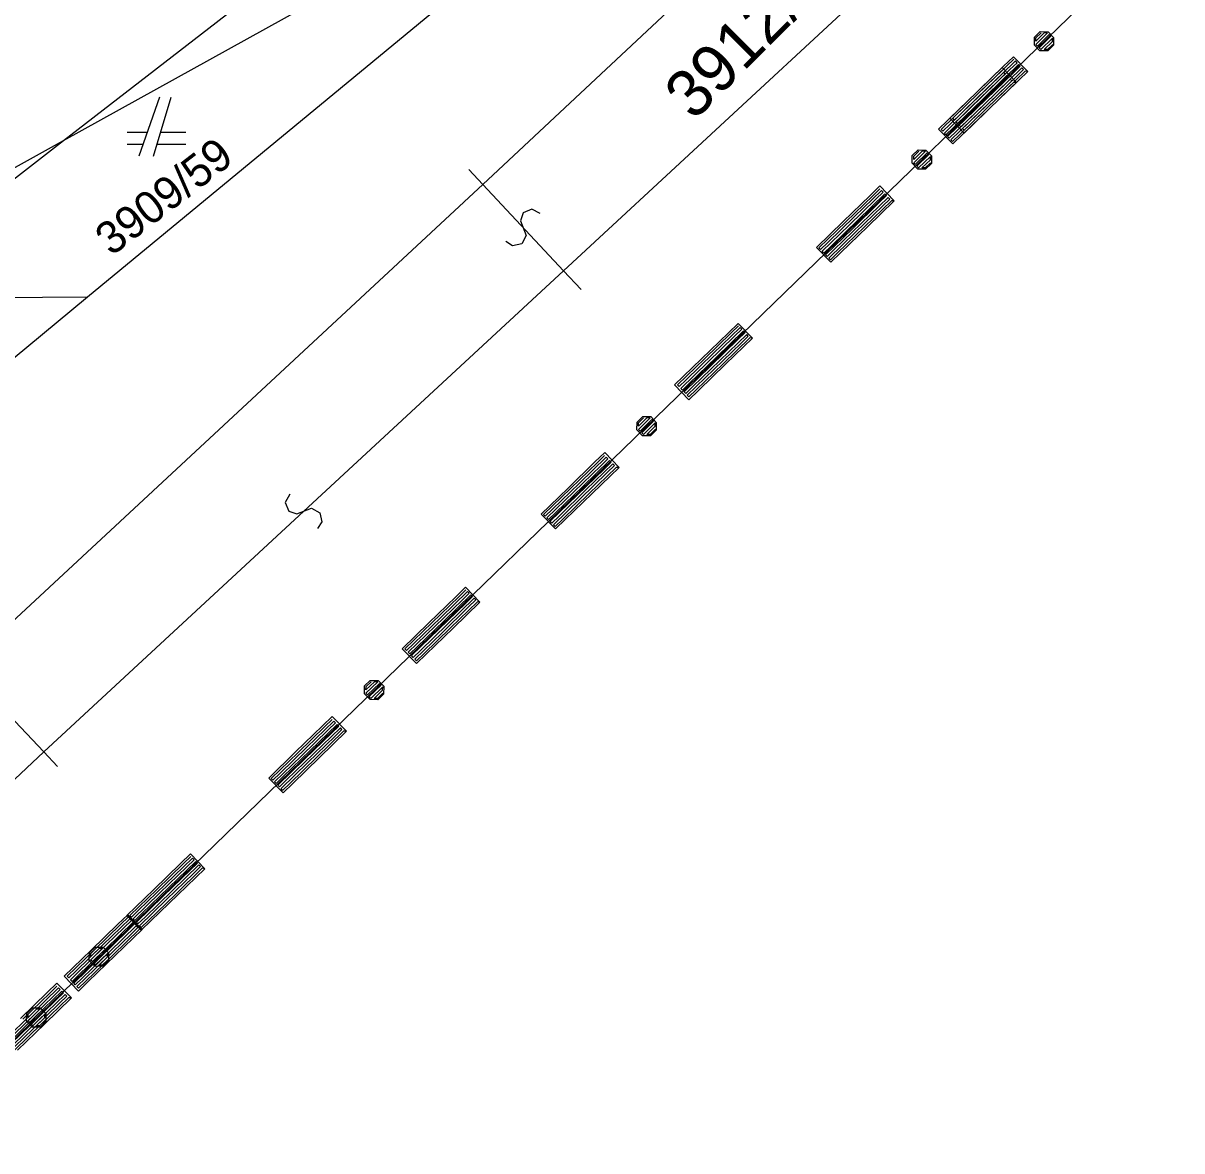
# Model space of a CAD drawing. Extents: x -266179 to -264727, y -1243225 to -1241702.
# Drawn here: x -265525.42 to -265486.12, y -1243104.16 to -1243065.9 of the extents above; entities that cross this region are included whole.
import ezdxf

# ---------------------------------------------------------------- set-up
doc = ezdxf.new("R2010")
doc.units = 0
for name, color, linetype in [('Vrstva 1', 7, 'Continuous'), ('Vrstva 19', 7, 'Continuous'), ('Vrstva 2', 7, 'Continuous'), ('Vrstva 21', 7, 'Continuous')]:
    doc.layers.add(name, color=color, linetype=linetype)

msp = doc.modelspace()

# ---------------------------------------------------------------- linework, layer by layer
at = {"layer": 'Vrstva 1'}
for p, q in [((-265524.05, -1243069.88), (-265501.93, -1243057.61)), ((-265501.93, -1243057.61), (-265523.24, -1243075.2)), ((-265486.12, -1243061.99), (-265499.6, -1243075.05)), ((-265520.8, -1243068.41), (-265521.5, -1243070.41)), ((-265521, -1243070.41), (-265520.4, -1243068.41)), ((-265521.22, -1243069.61), (-265521.9, -1243069.61)), ((-265519.9, -1243069.61), (-265520.76, -1243069.61)), ((-265533.77, -1243075.27), (-265524.05, -1243069.88)), ((-265521.9, -1243070.01), (-265521.36, -1243070.01)), ((-265520.88, -1243070.01), (-265519.9, -1243070.01)), ((-265523.24, -1243075.2), (-265536.52, -1243086.16)), ((-265523.24, -1243075.2), (-265530.95, -1243075.25)), ((-265499.6, -1243075.05), (-265518.18, -1243093.05)), ((-265518.18, -1243093.05), (-265529.64, -1243104.16))]:
    msp.add_line(p, q, dxfattribs=at)
at = {"layer": 'Vrstva 19'}
for p, q in [((-265486.12, -1243061.99), (-265499.6, -1243075.05)), ((-265499.6, -1243075.05), (-265518.18, -1243093.05)), ((-265518.18, -1243093.05), (-265529.64, -1243104.16))]:
    msp.add_line(p, q, dxfattribs=at)
for points in [[(-265490.472, -1243066.652), (-265490.666, -1243066.84), (-265490.935, -1243066.836), (-265491.123, -1243066.642), (-265491.118, -1243066.373), (-265490.925, -1243066.185), (-265490.656, -1243066.19), (-265490.468, -1243066.384), (-265490.472, -1243066.652), (-265490.507, -1243066.631), (-265490.68, -1243066.798), (-265490.793, -1243066.796), (-265490.506, -1243066.517), (-265490.504, -1243066.404), (-265490.906, -1243066.794), (-265490.962, -1243066.736), (-265490.559, -1243066.347), (-265490.615, -1243066.289), (-265491.017, -1243066.679), (-265491.073, -1243066.621), (-265490.671, -1243066.232), (-265490.784, -1243066.23), (-265491.071, -1243066.508), (-265491.069, -1243066.395), (-265490.897, -1243066.228)], [(-265491.73, -1243067.912), (-265492.642, -1243068.796), (-265493.555, -1243069.679), (-265493.885, -1243069.999), (-265494.372, -1243069.497), (-265493.46, -1243068.613), (-265492.548, -1243067.729), (-265492.217, -1243067.409), (-265491.73, -1243067.912), (-265491.829, -1243067.911), (-265492.741, -1243068.794), (-265493.654, -1243069.678), (-265493.898, -1243069.914), (-265493.953, -1243069.857), (-265493.041, -1243068.973), (-265492.129, -1243068.09), (-265491.885, -1243067.853), (-265491.94, -1243067.796), (-265492.853, -1243068.679), (-265493.765, -1243069.563), (-265494.009, -1243069.799), (-265494.065, -1243069.742), (-265493.153, -1243068.858), (-265492.24, -1243067.975), (-265491.996, -1243067.738), (-265492.052, -1243067.681), (-265492.964, -1243068.564), (-265493.876, -1243069.448), (-265494.12, -1243069.684), (-265494.176, -1243069.627), (-265493.264, -1243068.743), (-265492.352, -1243067.86), (-265492.107, -1243067.623), (-265492.163, -1243067.566), (-265493.075, -1243068.449), (-265493.988, -1243069.333), (-265494.232, -1243069.569), (-265494.287, -1243069.512), (-265493.375, -1243068.628), (-265492.463, -1243067.745), (-265492.219, -1243067.508)], [(-265491.348, -1243067.543), (-265492.26, -1243068.427), (-265493.172, -1243069.311), (-265493.503, -1243069.631), (-265493.99, -1243069.128), (-265493.078, -1243068.244), (-265492.165, -1243067.361), (-265491.835, -1243067.041), (-265491.348, -1243067.543), (-265491.433, -1243067.528), (-265492.345, -1243068.412), (-265493.257, -1243069.295), (-265493.501, -1243069.532), (-265493.557, -1243069.474), (-265492.645, -1243068.591), (-265491.732, -1243067.707), (-265491.488, -1243067.471), (-265491.544, -1243067.413), (-265492.456, -1243068.297), (-265493.368, -1243069.18), (-265493.613, -1243069.417), (-265493.668, -1243069.359), (-265492.756, -1243068.476), (-265491.844, -1243067.592), (-265491.6, -1243067.356), (-265491.655, -1243067.298), (-265492.567, -1243068.182), (-265493.48, -1243069.065), (-265493.724, -1243069.302), (-265493.78, -1243069.244), (-265492.867, -1243068.361), (-265491.955, -1243067.477), (-265491.711, -1243067.241), (-265491.767, -1243067.183), (-265492.679, -1243068.067), (-265493.591, -1243068.95), (-265493.835, -1243069.187), (-265493.891, -1243069.129), (-265492.979, -1243068.246), (-265492.066, -1243067.362), (-265491.822, -1243067.126)], [(-265494.616, -1243070.667), (-265494.81, -1243070.854), (-265495.078, -1243070.85), (-265495.266, -1243070.656), (-265495.262, -1243070.387), (-265495.068, -1243070.2), (-265494.799, -1243070.204), (-265494.611, -1243070.398), (-265494.616, -1243070.667), (-265494.651, -1243070.645), (-265494.823, -1243070.812), (-265494.936, -1243070.81), (-265494.649, -1243070.532), (-265494.647, -1243070.419), (-265495.049, -1243070.808), (-265495.105, -1243070.751), (-265494.703, -1243070.361), (-265494.758, -1243070.304), (-265495.161, -1243070.693), (-265495.216, -1243070.636), (-265494.814, -1243070.246), (-265494.927, -1243070.244), (-265495.214, -1243070.523), (-265495.213, -1243070.409), (-265495.04, -1243070.242)], [(-265495.873, -1243071.926), (-265496.786, -1243072.81), (-265497.698, -1243073.694), (-265498.028, -1243074.014), (-265498.515, -1243073.511), (-265497.603, -1243072.627), (-265496.691, -1243071.744), (-265496.36, -1243071.424), (-265495.873, -1243071.926), (-265495.972, -1243071.925), (-265496.885, -1243072.808), (-265497.797, -1243073.692), (-265498.041, -1243073.929), (-265498.097, -1243073.871), (-265497.185, -1243072.987), (-265496.272, -1243072.104), (-265496.028, -1243071.867), (-265496.084, -1243071.81), (-265496.996, -1243072.693), (-265497.908, -1243073.577), (-265498.152, -1243073.814), (-265498.208, -1243073.756), (-265497.296, -1243072.873), (-265496.384, -1243071.989), (-265496.139, -1243071.752), (-265496.195, -1243071.695), (-265497.107, -1243072.579), (-265498.02, -1243073.462), (-265498.264, -1243073.699), (-265498.319, -1243073.641), (-265497.407, -1243072.758), (-265496.495, -1243071.874), (-265496.251, -1243071.638), (-265496.306, -1243071.58), (-265497.219, -1243072.464), (-265498.131, -1243073.347), (-265498.375, -1243073.584), (-265498.431, -1243073.526), (-265497.518, -1243072.643), (-265496.606, -1243071.759), (-265496.362, -1243071.523)], [(-265500.685, -1243076.589), (-265501.597, -1243077.473), (-265502.509, -1243078.356), (-265502.84, -1243078.676), (-265503.327, -1243078.173), (-265502.414, -1243077.29), (-265501.502, -1243076.406), (-265501.172, -1243076.086), (-265500.685, -1243076.589), (-265500.769, -1243076.574), (-265501.682, -1243077.457), (-265502.594, -1243078.341), (-265502.838, -1243078.577), (-265502.894, -1243078.52), (-265501.982, -1243077.636), (-265501.069, -1243076.753), (-265500.825, -1243076.516), (-265500.881, -1243076.459), (-265501.793, -1243077.342), (-265502.705, -1243078.226), (-265502.949, -1243078.462), (-265503.005, -1243078.405), (-265502.093, -1243077.521), (-265501.181, -1243076.638), (-265500.936, -1243076.401), (-265500.992, -1243076.344), (-265501.904, -1243077.227), (-265502.817, -1243078.111), (-265503.061, -1243078.347), (-265503.116, -1243078.29), (-265502.204, -1243077.406), (-265501.292, -1243076.523), (-265501.048, -1243076.286), (-265501.103, -1243076.229), (-265502.016, -1243077.112), (-265502.928, -1243077.996), (-265503.172, -1243078.232), (-265503.228, -1243078.175), (-265502.315, -1243077.291), (-265501.403, -1243076.408), (-265501.159, -1243076.171)], [(-265503.952, -1243079.712), (-265504.146, -1243079.9), (-265504.415, -1243079.896), (-265504.603, -1243079.702), (-265504.599, -1243079.433), (-265504.405, -1243079.245), (-265504.136, -1243079.25), (-265503.948, -1243079.444), (-265503.952, -1243079.712), (-265503.987, -1243079.69), (-265504.16, -1243079.857), (-265504.273, -1243079.856), (-265503.986, -1243079.577), (-265503.984, -1243079.464), (-265504.386, -1243079.854), (-265504.442, -1243079.796), (-265504.04, -1243079.407), (-265504.095, -1243079.349), (-265504.497, -1243079.739), (-265504.553, -1243079.681), (-265504.151, -1243079.292), (-265504.264, -1243079.29), (-265504.551, -1243079.568), (-265504.549, -1243079.455), (-265504.377, -1243079.288)], [(-265505.21, -1243080.972), (-265506.122, -1243081.856), (-265507.035, -1243082.739), (-265507.365, -1243083.059), (-265507.852, -1243082.556), (-265506.94, -1243081.673), (-265506.028, -1243080.789), (-265505.697, -1243080.469), (-265505.21, -1243080.972), (-265505.309, -1243080.971), (-265506.221, -1243081.854), (-265507.134, -1243082.738), (-265507.378, -1243082.974), (-265507.434, -1243082.917), (-265506.521, -1243082.033), (-265505.609, -1243081.15), (-265505.365, -1243080.913), (-265505.421, -1243080.856), (-265506.333, -1243081.739), (-265507.245, -1243082.623), (-265507.489, -1243082.859), (-265507.545, -1243082.802), (-265506.633, -1243081.918), (-265505.72, -1243081.035), (-265505.476, -1243080.798), (-265505.532, -1243080.741), (-265506.444, -1243081.624), (-265507.356, -1243082.508), (-265507.601, -1243082.744), (-265507.656, -1243082.687), (-265506.744, -1243081.803), (-265505.832, -1243080.92), (-265505.587, -1243080.683), (-265505.643, -1243080.626), (-265506.555, -1243081.509), (-265507.468, -1243082.393), (-265507.712, -1243082.629), (-265507.768, -1243082.572), (-265506.855, -1243081.688), (-265505.943, -1243080.805), (-265505.699, -1243080.568)], [(-265509.928, -1243085.544), (-265510.84, -1243086.427), (-265511.752, -1243087.311), (-265512.083, -1243087.631), (-265512.57, -1243087.128), (-265511.658, -1243086.244), (-265510.745, -1243085.361), (-265510.415, -1243085.041), (-265509.928, -1243085.544), (-265510.012, -1243085.528), (-265510.925, -1243086.412), (-265511.837, -1243087.295), (-265512.081, -1243087.532), (-265512.137, -1243087.474), (-265511.225, -1243086.591), (-265510.312, -1243085.707), (-265510.068, -1243085.471), (-265510.124, -1243085.413), (-265511.036, -1243086.297), (-265511.948, -1243087.18), (-265512.193, -1243087.417), (-265512.248, -1243087.359), (-265511.336, -1243086.476), (-265510.424, -1243085.592), (-265510.179, -1243085.356), (-265510.235, -1243085.298), (-265511.147, -1243086.182), (-265512.06, -1243087.065), (-265512.304, -1243087.302), (-265512.359, -1243087.244), (-265511.447, -1243086.361), (-265510.535, -1243085.477), (-265510.291, -1243085.241), (-265510.346, -1243085.183), (-265511.259, -1243086.067), (-265512.171, -1243086.95), (-265512.415, -1243087.187), (-265512.471, -1243087.129), (-265511.559, -1243086.246), (-265510.646, -1243085.362), (-265510.402, -1243085.126)], [(-265513.196, -1243088.667), (-265513.389, -1243088.855), (-265513.658, -1243088.85), (-265513.846, -1243088.656), (-265513.842, -1243088.388), (-265513.648, -1243088.2), (-265513.379, -1243088.204), (-265513.191, -1243088.398), (-265513.196, -1243088.667), (-265513.231, -1243088.645), (-265513.403, -1243088.812), (-265513.516, -1243088.81), (-265513.229, -1243088.532), (-265513.227, -1243088.419), (-265513.629, -1243088.808), (-265513.685, -1243088.751), (-265513.283, -1243088.361), (-265513.338, -1243088.304), (-265513.74, -1243088.693), (-265513.796, -1243088.636), (-265513.394, -1243088.246), (-265513.507, -1243088.244), (-265513.794, -1243088.523), (-265513.793, -1243088.41), (-265513.62, -1243088.243)], [(-265514.453, -1243089.927), (-265515.366, -1243090.81), (-265516.278, -1243091.694), (-265516.608, -1243092.014), (-265517.095, -1243091.511), (-265516.183, -1243090.627), (-265515.271, -1243089.744), (-265514.94, -1243089.424), (-265514.453, -1243089.927), (-265514.552, -1243089.925), (-265515.465, -1243090.809), (-265516.377, -1243091.692), (-265516.621, -1243091.929), (-265516.677, -1243091.871), (-265515.764, -1243090.988), (-265514.852, -1243090.104), (-265514.608, -1243089.868), (-265514.664, -1243089.81), (-265515.576, -1243090.694), (-265516.488, -1243091.577), (-265516.732, -1243091.814), (-265516.788, -1243091.756), (-265515.876, -1243090.873), (-265514.963, -1243089.989), (-265514.719, -1243089.753), (-265514.775, -1243089.695), (-265515.687, -1243090.579), (-265516.599, -1243091.462), (-265516.844, -1243091.699), (-265516.899, -1243091.641), (-265515.987, -1243090.758), (-265515.075, -1243089.874), (-265514.831, -1243089.638), (-265514.886, -1243089.58), (-265515.798, -1243090.464), (-265516.711, -1243091.347), (-265516.955, -1243091.584), (-265517.011, -1243091.526), (-265516.098, -1243090.643), (-265515.186, -1243089.759), (-265514.942, -1243089.523)], [(-265519.263, -1243094.591), (-265520.175, -1243095.474), (-265521.088, -1243096.358), (-265521.418, -1243096.678), (-265521.905, -1243096.175), (-265520.993, -1243095.291), (-265520.081, -1243094.408), (-265519.75, -1243094.088), (-265519.263, -1243094.591), (-265519.348, -1243094.575), (-265520.26, -1243095.459), (-265521.172, -1243096.342), (-265521.417, -1243096.579), (-265521.472, -1243096.521), (-265520.56, -1243095.638), (-265519.648, -1243094.754), (-265519.403, -1243094.518), (-265519.459, -1243094.46), (-265520.371, -1243095.344), (-265521.284, -1243096.227), (-265521.528, -1243096.464), (-265521.584, -1243096.406), (-265520.671, -1243095.523), (-265519.759, -1243094.639), (-265519.515, -1243094.403), (-265519.57, -1243094.345), (-265520.483, -1243095.229), (-265521.395, -1243096.112), (-265521.639, -1243096.349), (-265521.695, -1243096.292), (-265520.783, -1243095.408), (-265519.87, -1243094.524), (-265519.626, -1243094.288), (-265519.682, -1243094.23), (-265520.594, -1243095.114), (-265521.506, -1243095.998), (-265521.751, -1243096.234), (-265521.806, -1243096.177), (-265520.894, -1243095.293), (-265519.982, -1243094.41), (-265519.737, -1243094.173)], [(-265521.389, -1243096.652), (-265522.302, -1243097.536), (-265523.214, -1243098.419), (-265523.544, -1243098.739), (-265524.031, -1243098.236), (-265523.119, -1243097.353), (-265522.207, -1243096.469), (-265521.876, -1243096.149), (-265521.389, -1243096.652), (-265521.474, -1243096.636), (-265522.386, -1243097.52), (-265523.299, -1243098.404), (-265523.543, -1243098.64), (-265523.598, -1243098.583), (-265522.686, -1243097.699), (-265521.774, -1243096.816), (-265521.53, -1243096.579), (-265521.585, -1243096.522), (-265522.498, -1243097.405), (-265523.41, -1243098.289), (-265523.654, -1243098.525), (-265523.71, -1243098.468), (-265522.797, -1243097.584), (-265521.885, -1243096.701), (-265521.641, -1243096.464), (-265521.697, -1243096.407), (-265522.609, -1243097.29), (-265523.521, -1243098.174), (-265523.765, -1243098.41), (-265523.821, -1243098.353), (-265522.909, -1243097.469), (-265521.997, -1243096.586), (-265521.752, -1243096.349), (-265521.808, -1243096.292), (-265522.72, -1243097.175), (-265523.632, -1243098.059), (-265523.877, -1243098.295), (-265523.932, -1243098.238), (-265523.02, -1243097.354), (-265522.108, -1243096.471), (-265521.864, -1243096.234)], [(-265522.531, -1243097.714), (-265522.725, -1243097.902), (-265522.994, -1243097.897), (-265523.181, -1243097.703), (-265523.177, -1243097.435), (-265522.983, -1243097.247), (-265522.714, -1243097.251), (-265522.527, -1243097.445), (-265522.531, -1243097.714), (-265522.566, -1243097.692), (-265522.738, -1243097.859), (-265522.851, -1243097.857), (-265522.564, -1243097.579), (-265522.562, -1243097.466), (-265522.965, -1243097.855), (-265523.02, -1243097.798), (-265522.618, -1243097.408), (-265522.674, -1243097.351), (-265523.076, -1243097.74), (-265523.132, -1243097.683), (-265522.729, -1243097.293), (-265522.842, -1243097.292), (-265523.13, -1243097.57), (-265523.128, -1243097.457), (-265522.956, -1243097.29)], [(-265525.518, -1243099.674), (-265524.606, -1243098.791), (-265524.276, -1243098.471), (-265523.789, -1243098.974), (-265523.888, -1243098.972), (-265524.8, -1243099.856), (-265525.712, -1243100.739)], [(-265526.235, -1243100.688), (-265525.322, -1243099.805), (-265524.41, -1243098.921), (-265524.166, -1243098.685), (-265524.222, -1243098.627), (-265525.134, -1243099.511), (-265526.046, -1243100.394)], [(-265526.123, -1243100.803), (-265525.211, -1243099.92), (-265524.299, -1243099.036), (-265524.055, -1243098.8), (-265524.11, -1243098.742), (-265525.023, -1243099.626), (-265525.935, -1243100.509)], [(-265526.012, -1243100.918), (-265525.1, -1243100.035), (-265524.188, -1243099.151), (-265523.943, -1243098.915), (-265523.999, -1243098.857), (-265524.911, -1243099.741), (-265525.823, -1243100.624)], [(-265525.434, -1243099.69), (-265524.521, -1243098.806), (-265524.277, -1243098.57)], [(-265523.789, -1243098.974), (-265524.701, -1243099.857), (-265525.613, -1243100.741)], [(-265524.657, -1243099.775), (-265524.851, -1243099.963), (-265525.12, -1243099.959), (-265525.308, -1243099.765), (-265525.303, -1243099.496), (-265525.109, -1243099.308), (-265524.841, -1243099.312), (-265524.653, -1243099.506), (-265524.657, -1243099.775), (-265524.692, -1243099.753), (-265524.864, -1243099.92), (-265524.978, -1243099.918), (-265524.69, -1243099.64), (-265524.688, -1243099.527), (-265525.091, -1243099.917), (-265525.146, -1243099.859), (-265524.744, -1243099.47), (-265524.8, -1243099.412), (-265525.202, -1243099.802), (-265525.258, -1243099.744), (-265524.855, -1243099.355), (-265524.969, -1243099.353), (-265525.256, -1243099.631), (-265525.254, -1243099.518), (-265525.082, -1243099.351)]]:
    msp.add_lwpolyline(points, dxfattribs=at)
at = {"layer": 'Vrstva 2'}
for p, q in [((-265524.05, -1243069.88), (-265488.71, -1243042.52)), ((-265509.83, -1243071.37), (-265492.37, -1243055.04)), ((-265507.1, -1243074.3), (-265489.57, -1243058.08)), ((-265527.5, -1243072.55), (-265524.05, -1243069.88)), ((-265510.31, -1243070.86), (-265509.83, -1243071.37)), ((-265527.45, -1243087.75), (-265509.83, -1243071.37)), ((-265509.83, -1243071.37), (-265507.1, -1243074.3)), ((-265524.72, -1243090.62), (-265507.1, -1243074.3)), ((-265507.1, -1243074.3), (-265506.5, -1243074.94)), ((-265527.45, -1243087.75), (-265524.72, -1243090.62)), ((-265539.15, -1243104.16), (-265524.72, -1243090.62)), ((-265524.72, -1243090.62), (-265524.26, -1243091.12))]:
    msp.add_line(p, q, dxfattribs=at)
for points in [[(-265507.882, -1243072.361), (-265508.174, -1243072.209), (-265508.468, -1243072.333), (-265508.556, -1243072.605), (-265508.362, -1243073.108), (-265508.513, -1243073.385), (-265508.82, -1243073.452), (-265509.048, -1243073.309)], [(-265516.383, -1243081.876), (-265516.536, -1243082.167), (-265516.412, -1243082.462), (-265516.14, -1243082.55), (-265515.637, -1243082.357), (-265515.36, -1243082.509), (-265515.294, -1243082.816), (-265515.437, -1243083.044)]]:
    msp.add_lwpolyline(points, dxfattribs=at)
at = {"layer": 'Vrstva 21'}
for p, q in [((-265486.12, -1243061.99), (-265499.6, -1243075.05)), ((-265499.6, -1243075.05), (-265518.18, -1243093.05)), ((-265518.18, -1243093.05), (-265529.64, -1243104.16))]:
    msp.add_line(p, q, dxfattribs=at)

# ---------------------------------------------------------------- texts
at = {"layer": 'Vrstva 1'}
for s, height, rotation, p in [('3912/8', 1.6, 44.9772, (-265502.672, -1243069.243)), ('3909/59', 1.1, 37.6433, (-265522.426, -1243073.827))]:
    msp.add_text(s, height=height, rotation=rotation, dxfattribs=at).set_placement(p)

doc.saveas('drawing.dxf')
